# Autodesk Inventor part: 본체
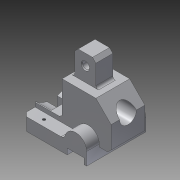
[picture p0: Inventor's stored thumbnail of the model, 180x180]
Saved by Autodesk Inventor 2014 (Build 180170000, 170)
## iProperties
Created: 2016-11
Part Number: 본체
Material: 알루미늄 6061
Document SubType Name: Modeling
Designer: USER
Density: 2.71 g/cm^3
Appearance: 알루미늄 - 평지
Mass: 477.197 g
Surface Area: 324.806 cm^2
Volume: 176.087 cm^3
Author: USER
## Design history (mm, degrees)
sketch "스케치1"
  geometry: L1 (0, 0)-(0, -30); L2 (0, 0)-(18, 18); L3 (18, 18)-(58, 18); L4 (58, 18)-(58, -22); L5 (58, -22)-(90, -22); L6 (90, -22)-(90, -30); L7 (90, -30)-(0, -30)
  constraints: 14 end point, 5 perpendicular, 1 vertical
  dimensions: "d1" = 48 vertical distance of L1.end L2.end; "d2" = 45 deg angle of L3 L2; "d3" = 90 distance of L6.end L1.end; "d4" = 58 horizontal distance of L3.end L1.start; "d5" = 8 distance between parallel lines of L7 L5; "d75" = 18 horizontal distance of L2.end L1.start
extrude "돌출1" new body sketch "스케치1" stored distance "d6" = 40; taper "d7" = 0 deg
sketch "스케치3"
  geometry: L1 (58, 18)-(18, 18) reference; L2 (28, 18)-(53, 18); L3 (53, 18)-(53, 48); L4 (53, 48)-(28, 48); L5 (28, 48)-(28, 18); L6 (58, 18)-(58, -22) reference; 1 further point
  constraints: 8 end point, 2 parallel, 1 horizontal, 1 perpendicular, 1 point on line
  dimensions: "d9" = 25 distance of L3.end L4.end; "d10" = 5 distance between parallel lines of L6 L3; "d11" = 30 distance between parallel lines of L1 L4
extrude "돌출2" join sketch "스케치3" stored distance "d12" = 20; taper "d13" = 0 deg
chamfer "모따기1" distance "d14" = 4; stored, may be unused: second distance "d15" = 2, angle "d16" = 45 deg
sketch "스케치5"
  geometry: L1 (58, -22)-(90, -22) reference; L2 (90, -42)-(37, -42); L3 (90, -27)-(40, -27); L4 (14, -27)-(14, -42); L5 (14, -42)-(17, -42); L6 (37, -42)-(37, -35); L7 (37, -35)-(17, -35); L8 (17, -35)-(17, -42); L9 (90, -42)-(90, -27); A1 r 13 centre (27, -27) between (40, -27) and (14, -27); 1 further point
  constraints: 16 end point, 3 horizontal alignment, 3 perpendicular, 2 parallel, 2 point on circle, 1 centre point, 1 tangent, 1 vertical alignment
  dimensions: "d18" = 26 diameter of A1; "d20" = 15 distance from line of L2 A1.centre; "d22" = 15 distance of L4.start L4.end; "d23" = 3 distance of L4.end L5.end; "d26" = 7 distance of L2.end L6.end; "d27" = 20 distance of L6.end L7.end; "d28" = 76 distance from line of L4.start L9; "d76" = 20 distance between parallel lines of L2 L1
extrude "돌출3" join sketch "스케치5" stored distance "d29" = 70; taper "d30" = 0 deg
sketch "스케치7"
  geometry: L1 (-60, -15)-(-60, 55) reference; L2 (-45, 40)-(-45, 40) reference; L3 (-45, 0)-(-45, -15) reference; L4 (-45, 55)-(-45, 55) reference; L5 (-45, 55)-(-45, 40) reference; L6 (-32, 40)-(-32, 55) reference; L7 (-45, 55)-(-45, 40) reference; L8 (-45, 0)-(-45, 0) reference; L9 (-45, 0)-(-45, -15) reference; L10 (-45, -15)-(-45, -15) reference; C1 r 14.5 at (-18, 20); 1 further point
  constraints: 2 coincident, 1 centre point
  dimensions: "d31" = 29 diameter of C1
extrude "돌출4" cut sketch "스케치7" distance "d33" = 7; taper "d34" = 0 deg
sketch "스케치8"
  geometry: C1 r 14.5 at (0, 0) reference; C2 r 10 at (0, 0); 1 further point
  constraints: 1 centre point, 1 coincident
  dimensions: "d35" = 20 diameter of C2
extrude "돌출5" cut sketch "스케치8" distance "d36" = 124.5; taper "d37" = 0 deg
chamfer "모따기2" distance "d38" = 1; stored, may be unused: second distance "d39" = 2, angle "d40" = 45 deg
node "작업 평면1"
sketch "스케치9"
  geometry: L1 (-20, 55)-(-20, -15) reference; L2 (-6.373, 26)-(-20, 26); L3 (-20, 26)-(-20, 14); L4 (-20, 14)-(-6.373, 14); L5 (0, 0)-(0, 40) reference; L6 (0, 38.894)-(0, 1.106); C1 r 14.5 at (22, 20) reference; A1 r 29 centre (22, 20) between (0, 38.894) and (-6.373, 26); A2 r 29 centre (22, 20) between (-6.373, 14) and (0, 1.106); 2 further points
  constraints: 8 end point, 4 point on circle, 4 point on line, 2 centre point, 2 perpendicular, 1 coincident, 1 collinear, 1 horizontal alignment, 1 midpoint
  dimensions: "d43" = 12 distance of L3.end L2.end; "d44" = 29 radius of A1; "d45" = 29 radius of A2
extrude "돌출6" cut sketch "스케치9" distance "d46" = 97; taper "d47" = 0 deg
sketch "스케치10"
  geometry: L1 (0, 15)-(0, 0) reference; L2 (18, 7.5)-(18, -47.5); 2 further points
  constraints: 2 end point, 1 horizontal alignment, 1 midpoint, 1 parallel, 1 vertical alignment
  dimensions: "d48" = 18 distance from line of L2.start L1; "d49" = 55 distance of L2.end L2.start
hole "구멍1" sketch "스케치10" at (18, 7.5), (18, -47.5) diameter "d50" = 3.242; stored, may be unused: countersink angle "d54" = 90 deg, drill point angle "d56" = 118 deg; dims "d51" = 20, "d52" = 4, "d53" = 2, "d55" = 8
sketch "스케치11"
  geometry: L1 (-28, -44)-(-28, -18) reference; L2 (-37, 42)-(-90, 42) reference; C1 r 4 at (-40.5, -35); 1 further point
  constraints: 1 centre point
  dimensions: "d57" = 8 diameter of C1; "d58" = 12.5 distance from line of L1 C1.centre; "d59" = 77 distance from line of L2 C1.centre
extrude "돌출7" cut sketch "스케치11" distance "d60" = 97; taper "d61" = 0 deg
chamfer "모따기3" distance "d62" = 1; stored, may be unused: second distance "d63" = 2, angle "d64" = 45 deg
fillet "모깎기1" dims "d65" = 3
fillet "모깎기2" dims "d66" = 5
fillet "모깎기3" dims "d67" = 3
sketch "스케치12"
  geometry: L1 (-58, 19)-(-58, -18) reference; L2 (-58, -18)-(-18, -18) reference; 1 further point
  constraints: 1 other
  dimensions: "d68" = 18 distance from line of L2 point (-33, 0); "d69" = 25 distance from line of L1 point (-33, 0)
feature "엠보싱1" sketch "스케치12" dims "d70" = 0.5, "d71" = 0
chamfer "모따기4" distance "d72" = 5; stored, may be unused: second distance "d73" = 2, angle "d74" = 45 deg
node "솔리드1"
node "투영된 루프1"
other parameters: "d41" = -18, "d42" = 58
